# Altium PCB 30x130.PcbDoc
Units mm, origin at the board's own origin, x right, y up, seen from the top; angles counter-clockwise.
Board outline 127 x 31.6 mm, 4 copper layers (Top Layer, Internal Plane 1, Internal Plane 2, Bottom Layer); 12 components, 8 nets, 22 pads, 0 vias.
Unrouted connection lines stored in the file: 1.
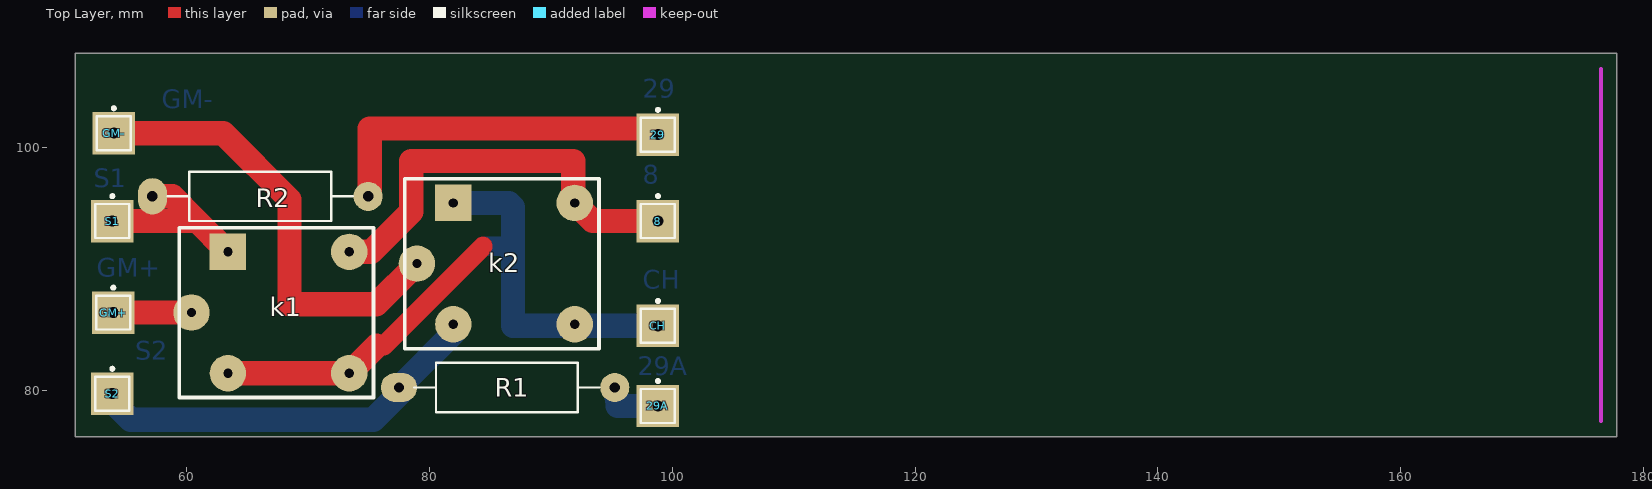
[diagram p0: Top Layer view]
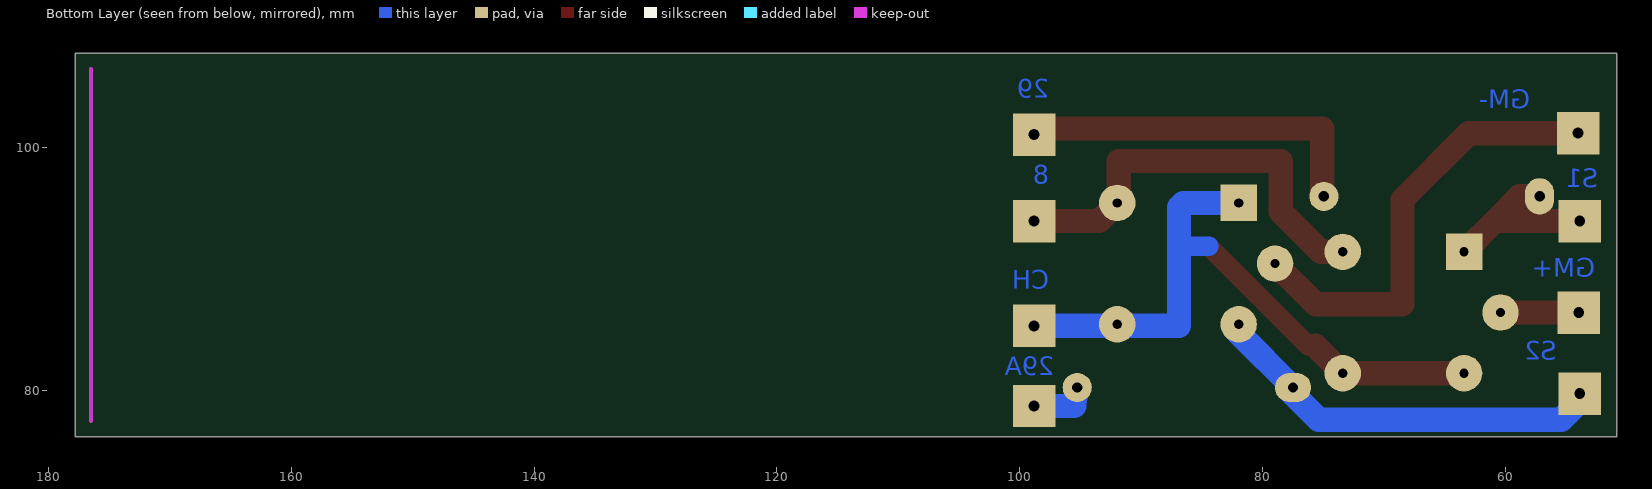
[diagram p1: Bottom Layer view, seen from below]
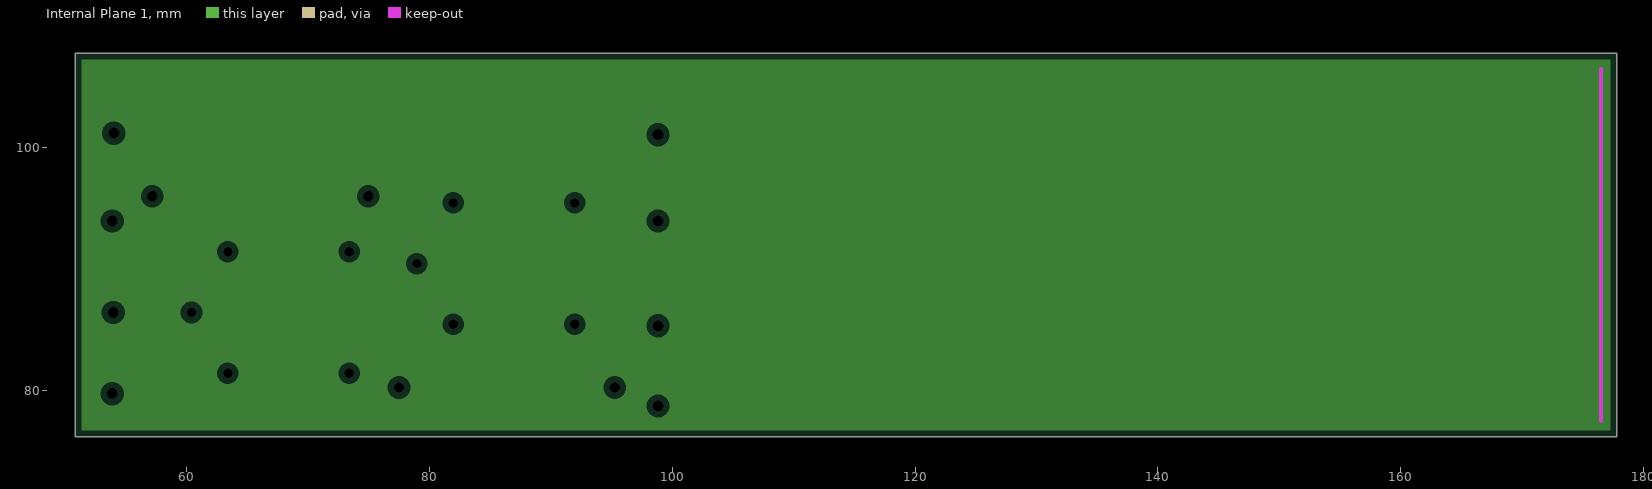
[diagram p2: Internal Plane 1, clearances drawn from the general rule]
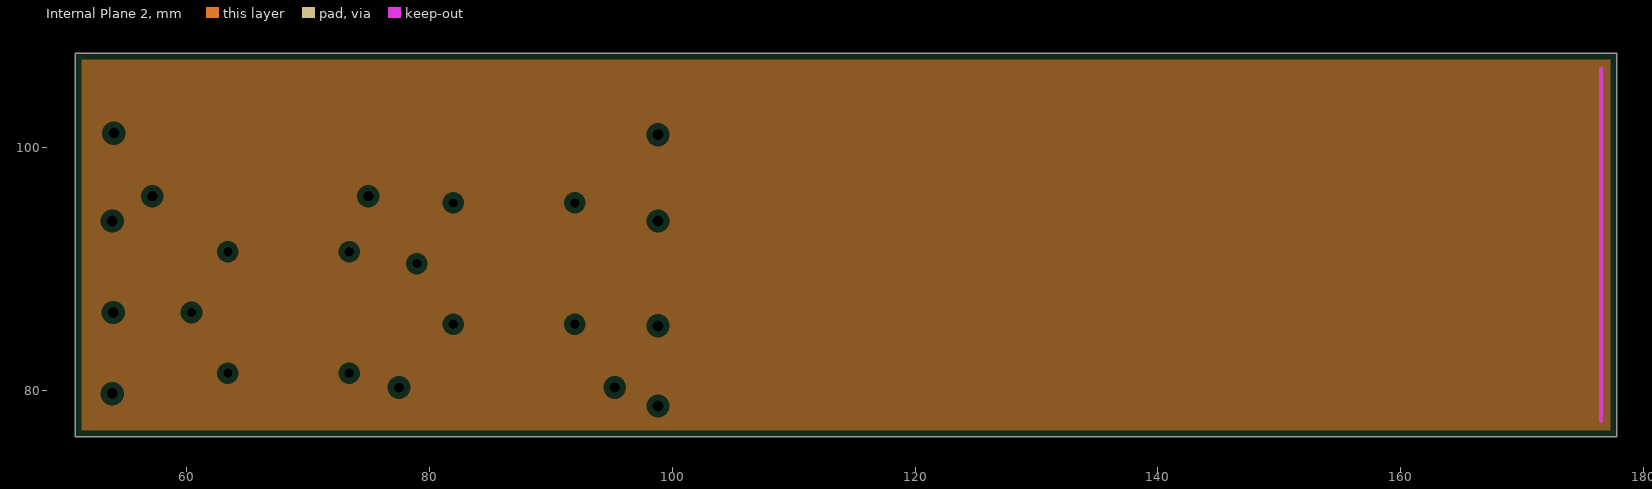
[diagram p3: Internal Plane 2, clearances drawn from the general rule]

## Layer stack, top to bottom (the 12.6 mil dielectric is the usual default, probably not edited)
Top Layer: signal copper 0.0356
Dielectric: dielectric 0.32, FR-4, Dk 4.8
Internal Plane 1: plane copper 0.0356
Dielectric: dielectric 0.32, FR-4, Dk 4.8
Internal Plane 2: plane copper 0.0356
Dielectric: dielectric 0.32, FR-4, Dk 4.8
Bottom Layer: signal copper 0.0356

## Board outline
50.8,76.2 177.8,76.2 177.8,107.8 50.8,107.8

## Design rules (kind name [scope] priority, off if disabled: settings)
Clearance [All] p1: gap=0.5
PlaneClearance [All] p1: clearance=0.508
PlaneConnect [All] p1: planeconnectstyle=Relief reliefexpansion=0.508 reliefentries=4 reliefconductorwidth=0.254 reliefairgap=0.254
PolygonConnect [All] p1: connectstyle=Relief reliefconductorwidth=0.254 reliefentries=4 polygonreliefangle="90 Angle"
RoomDefinition Sheet1 [InComponentClass('Sheet1')] p1: confinementstyle=ConfineIn formatcopy=TRUE lockcomponents=FALSE outline 51.943,76.581 139.7,76.581 139.7,106.807 51.943,106.807
RoutingVias [All] p1: holewidth=2 width=2 viastyle="Through Hole" minholewidth=0.711 minwidth=1.27 maxholewidth=3.711 maxwidth=3.27
SolderMaskExpansion [All] p1: expansion=0.102
TestPointUsage [All] p1: valid=0 allowmultiple=FALSE
Testpoint [All] p1: side=15 testpointundercomponent=TRUE minsize=1.016 maxsize=2.54 preferedsize=1.524 minholesize=0 maxholesize=1.016 preferedholesize=0.813 testpointgrid=0.025 style=1023 order=0123456789
Width [All] p1: maxlimit=4 minlimit=0.8 preferedwidth=0.8 minimp=50.000000 maximp=50.000000 favimp=50.000000
17 further rules are at their usual default settings.

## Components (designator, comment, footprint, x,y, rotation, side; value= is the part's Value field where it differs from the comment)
8 "8" PIN1 98.806,93.98 r0 top (schematic designator P3)
29 "29A" PIN1 98.806,101.092 r0 top (schematic designator P1)
29A "29" PIN1 98.806,78.74 r0 top (schematic designator P2)
CH "CH" PIN1 98.806,85.344 r0 top (schematic designator P4)
GM+ "Motor" PIN1 53.929,86.44 r0 top (schematic designator P5)
GM- "Motor" PIN1 53.975,101.219 r0 top (schematic designator P6)
k1 "Component_1" PCBComponent_1 56.373,78.44 r0 top
k2 "Component_1" PCBComponent_1 74.948,82.471 r0 top
R1 "Res2" AXIAL-0.7#1 86.36,80.264 r180 top
R2 "Res2" AXIAL-0.7#2 66.04,96.012 r180 top
S1 "S1" PIN1 53.848,93.98 r0 top (schematic designator P7)
S2 "S2" PIN1 53.848,79.756 r0 top (schematic designator P8)

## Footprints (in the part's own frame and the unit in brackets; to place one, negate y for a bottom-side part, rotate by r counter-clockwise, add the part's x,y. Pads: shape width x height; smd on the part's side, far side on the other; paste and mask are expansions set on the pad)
AXIAL-0.7#1 [mm] "Variable Resistor; 2 Leads"
  round 2.4 hole 0.85: 1(-8.89,0)
  oval 3x2.4 hole 0.85: 2(8.89,0)
  silkscreen extent -7.62,-2.03 7.62,2.03
AXIAL-0.7#2 [mm] "Variable Resistor; 2 Leads"
  round 2.4 hole 0.85: 1(-8.89,0)
  oval 2.4x3 hole 0.85: 2(8.89,0)
  silkscreen extent -7.62,-2.03 7.62,2.03
PCBComponent_1 [mm]
  rect 3x3 hole 0.762: 1(7,13)
  round 3 hole 0.762: 2(7,3) 3(4,8) 4(17,13) 5(17,3)
  silkscreen extent 3,1 19,15, body extent 3,1 19,15, height 12.5
PIN1 [mm] "Connector; Plug"
  rect 3.5x3.5 hole 0.9: 1(0,0)
  silkscreen extent -1.4,-1.4 1.4,2.17

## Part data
8 29 29A CH GM+ GM- S1 S2: library part Plug, "Plug"
R1 R2: "Resistor"

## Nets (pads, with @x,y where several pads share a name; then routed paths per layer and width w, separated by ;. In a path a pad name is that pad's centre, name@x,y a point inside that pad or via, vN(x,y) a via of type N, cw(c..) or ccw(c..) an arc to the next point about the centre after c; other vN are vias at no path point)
GND: CH.1 k1.2 k1.5 k2.1 k2.5 | length 54
  Top Layer w1.6: 76.2,83.693 84.391,91.885
  Top Layer w2: k1.2 k1.5 75.626,83.693
  Bottom Layer w1.6: 84.391,91.885 86.868,91.885
  Bottom Layer w2: k2.1 86.52,95.471 86.868,95.123 86.868,91.885 86.868,85.344 91.948,85.344 CH.1
Netk1_1: k1.1 R2.2 S1.1 | length 15
  Top Layer w2: S1.1 60.5,93.98 60.666,94.147 ; R2.2 58.801,96.012 60.666,94.147 ; k1.1 60.666,94.147
Netk1_3: GM+.1 k1.3 | length 6.4
  Top Layer w2: GM+.1 k1.3
Netk1_4: 8.1 k1.4 k2.4 | length 35
  Top Layer w2: k1.4 75.184,91.44 78.486,94.742 78.486,98.933 91.821,98.933 91.821,95.598 k2.4 93.439,93.98 8.1
Netk2_2: k2.2 R1.2 S2.1 | length 32
  Bottom Layer w2: S2.1@53.721,79.248 55.372,77.597 75.344,77.597 R1.2@77.74,79.993 ; R1.2 k2.2@81.948,84.742
Netk2_3: GM-.1 k2.3 | length 37.3
  Top Layer w2: GM-.1 62.992,101.219 68.453,95.758 68.453,87.122 75.599,87.122 k2.3
NetP1_1: 29.1 R2.1 | length 29.5
  Top Layer w2: R2.1@75.057,96.012 75.057,101.6 98.298,101.6 29.1
NetP2_1: 29A.1 R1.1 | length 4.8
  Bottom Layer w2: R1.1 95.504,78.74 29A.1

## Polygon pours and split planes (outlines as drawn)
no net on Internal Plane 1 (split plane): 177.29,76.71 51.31,76.71 51.31,107.29 177.29,107.29
no net on Internal Plane 2 (split plane): 177.29,76.71 51.31,76.71 51.31,107.29 177.29,107.29

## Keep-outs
Keep-Out Layer:
  lines w0.3: 176.5,77.5 176.5,106.5

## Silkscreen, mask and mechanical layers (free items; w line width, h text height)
Drill Drawing:
  text ".LEGEND" at 182.88,81.28 h1.52
  text "Drill Drawing." at 182.88,78.74 h1.52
